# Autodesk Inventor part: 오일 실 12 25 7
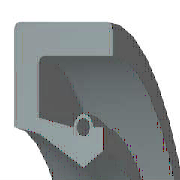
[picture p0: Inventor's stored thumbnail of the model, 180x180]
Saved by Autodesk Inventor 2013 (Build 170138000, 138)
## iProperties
IsCustomPart: 1
Created: 2012-02
Part Number: 오일 실 12 25 7
Material: 고무
Description: 오일-실
Document SubType Name: Modeling
Standard: KS B 2804
Designer: mduedu
Standards Organization: KS
Language: ko-KR
Size Designation: S - 12 25 7
Categories: <MemberInstance><Categories><Category DisplayName="샤프트 부품" InternalName="7f7aeb1f-a693-4053-b835-cee3144e0d98" Mnemonic="SHFT"><Category DisplayName="실링" Intern
Density: 0.93 g/cm^3
Author: mduedu
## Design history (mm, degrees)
revolve "본체" stored, may be unused: angle "d17" = 90 deg
revolve "스프링1" stored, may be unused: angle "d18" = 90 deg
body "Solid1"
sketch "스케치1"
  geometry: L1 (0, 12.5)-(7, 12.5); L2 (7, 12.5)-(7, 11.25); L3 (7, 11.25)-(1.75, 11.25); L4 (0, 12.5)-(0, 8.1); L5 (0, 8.1)-(1.75, 7.75); L6 (1.75, 7.75)-(4.9, 6); L7 (4.9, 6)-(0, 6); L8 (6.3, 6.875)-(6.3, 8.1); L9 (0, 0)-(9.586, 0) reference; L10 (4.9, 6)-(6.3, 6.875); L11 (0, 18)-(0, -3) reference; L12 (-1.917, 0)-(11.503, 0) reference; L13 (4.2, 8.1)-(1.75, 8.59); L14 (1.75, 8.59)-(1.75, 11.25); L15 (6.3, 8.1)-(5.6, 8.1); C1 r 0.455 at (4.9, 8.1); A1 r 0.7 centre (4.9, 8.1) between (5.6, 8.1) and (4.2, 8.1)
  constraints: 26 end point, 5 horizontal alignment, 4 perpendicular, 2 centre point, 2 collinear, 2 horizontal, 2 parallel, 2 point on circle, 2 point on line, 2 vertical alignment, 1 coincident
  dimensions: "d0" = 25 diameter of L1 L9 (= SD2); "d1" = 13.75 diameter of L8.start L9 (= ABDM); "d2" = 1.25 distance of L1.end L2.end (computed from SD); "d3" = 0.91 diameter of C1 (= SPDI); "d4" = 1.4 diameter of A1 (= SPDA); "d5" = 12 diameter of L6.end L9 (= NND); "d6" = 15.5 diameter of L5.end L9 (= TKDM); "d7" = 16.2 diameter of L4.end L9 (= HLDM); "d8" = 4.9 distance from line of C1.centre L4 (= SPDST); "d9" = 6.3 distance between parallel lines of L8 L4 (= SDI); "d10" = 7 distance between parallel lines of L2 L4 (= SWDT); "d12" = 1.75 distance between parallel lines of L14 L4 (= SD)
fillet "모깎기1" dims "d11" = 0.3 (= RR)
other parameters: "SD2" = 25 [user parameter; used in 1 equation term], "SWDT" = 7 [user parameter; used in 1 equation term], "RR" = 0.3 [user parameter; used in 1 equation term], "SD" = 1.75 [user parameter; used in 2 equation terms], "NND" = 12 [user parameter; used in 1 equation term], "SPDA" = 1.4 [user parameter; used in 1 equation term], "SPDI" = 0.91 [user parameter; used in 1 equation term], "TKDM" = 15.5 [user parameter; used in 1 equation term], "HLDM" = 16.2 [user parameter; used in 1 equation term], "ABDM" = 13.75 [user parameter; used in 1 equation term], "SDI" = 6.3 [user parameter; used in 1 equation term], "SPDST" = 4.9 [user parameter; used in 1 equation term], "d13" = 0, "d14" = 0, "d15" = 0, "LAB" = 0.35 [user parameter]
